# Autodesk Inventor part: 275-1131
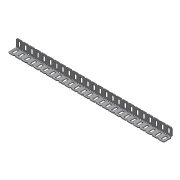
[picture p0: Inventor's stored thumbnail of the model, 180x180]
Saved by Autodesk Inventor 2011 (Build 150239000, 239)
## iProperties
Company: Autodesk Inc.
Created: 2005-08
Part Number: 275-1131
Document SubType Name: Sheet Metal
Designer: Autodesk Inc.
Density: 1 g/cm^3
Sheet Metal Rule: Default
Catalog Web Link: http://www.vexrobotics.com/products/accessories/structure/275-1131.html
Description: VEX angle without slots. Typically used for structural framing. Good strength on two axis.
Vendor: Innovation First, Inc.
Author: Autodesk Inc.
Title: VEX Robotics Kit of Parts
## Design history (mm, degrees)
node "Face1"
  sketch "Sketch1" dims "d23" = 25.4
    geometry: L1 (-154.686, 13.081)-(-150.114, 13.081); L2 (-150.114, 13.081)-(-150.114, 3.302); L3 (-150.114, 3.302)-(-154.686, 3.302); L4 (-154.686, 3.302)-(-154.686, 13.081); L5 (-158.75, 14.605)-(-158.75, 0); L6 (158.75, 14.605)-(158.75, 0); L7 (-158.75, 0)-(158.75, 0); L8 (-156.845, 16.51)-(-158.75, 14.605); L9 (-141.986, 3.302)-(-141.986, 13.081); L10 (-137.414, 3.302)-(-141.986, 3.302); L11 (-137.414, 13.081)-(-137.414, 3.302); L12 (-141.986, 13.081)-(-137.414, 13.081); L13 (-129.286, 3.302)-(-129.286, 13.081); L14 (-124.714, 3.302)-(-129.286, 3.302); L15 (-124.714, 13.081)-(-124.714, 3.302); L16 (-129.286, 13.081)-(-124.714, 13.081); L17 (-116.586, 3.302)-(-116.586, 13.081); L18 (-112.014, 3.302)-(-116.586, 3.302); L19 (-112.014, 13.081)-(-112.014, 3.302); L20 (-116.586, 13.081)-(-112.014, 13.081); L21 (-103.886, 3.302)-(-103.886, 13.081); L22 (-99.314, 3.302)-(-103.886, 3.302); L23 (-99.314, 13.081)-(-99.314, 3.302); L24 (-103.886, 13.081)-(-99.314, 13.081); L25 (-91.186, 3.302)-(-91.186, 13.081); L26 (-86.614, 3.302)-(-91.186, 3.302); L27 (-86.614, 13.081)-(-86.614, 3.302); L28 (-91.186, 13.081)-(-86.614, 13.081); L29 (-78.486, 3.302)-(-78.486, 13.081); L30 (-73.914, 3.302)-(-78.486, 3.302); L31 (-73.914, 13.081)-(-73.914, 3.302); L32 (-78.486, 13.081)-(-73.914, 13.081); L33 (-65.786, 3.302)-(-65.786, 13.081); L34 (-61.214, 3.302)-(-65.786, 3.302); L35 (-61.214, 13.081)-(-61.214, 3.302); L36 (-65.786, 13.081)-(-61.214, 13.081); L37 (-53.086, 3.302)-(-53.086, 13.081); L38 (-48.514, 3.302)-(-53.086, 3.302); L39 (-48.514, 13.081)-(-48.514, 3.302); L40 (-53.086, 13.081)-(-48.514, 13.081); L41 (-40.386, 3.302)-(-40.386, 13.081); L42 (-35.814, 3.302)-(-40.386, 3.302); L43 (-35.814, 13.081)-(-35.814, 3.302); L44 (-40.386, 13.081)-(-35.814, 13.081); L45 (-27.686, 3.302)-(-27.686, 13.081); L46 (-23.114, 3.302)-(-27.686, 3.302); L47 (-23.114, 13.081)-(-23.114, 3.302); L48 (-27.686, 13.081)-(-23.114, 13.081); L49 (-14.986, 3.302)-(-14.986, 13.081); L50 (-10.414, 3.302)-(-14.986, 3.302); L51 (-10.414, 13.081)-(-10.414, 3.302); L52 (-14.986, 13.081)-(-10.414, 13.081); L53 (-2.286, 3.302)-(-2.286, 13.081); L54 (2.286, 3.302)-(-2.286, 3.302); L55 (2.286, 13.081)-(2.286, 3.302); L56 (-2.286, 13.081)-(2.286, 13.081); L57 (10.414, 3.302)-(10.414, 13.081); L58 (14.986, 3.302)-(10.414, 3.302); L59 (14.986, 13.081)-(14.986, 3.302); L60 (10.414, 13.081)-(14.986, 13.081); L61 (23.114, 3.302)-(23.114, 13.081); L62 (27.686, 3.302)-(23.114, 3.302); L63 (27.686, 13.081)-(27.686, 3.302); L64 (23.114, 13.081)-(27.686, 13.081)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; 4 further points
    constraints: 212 end point, 5 parallel, 2 horizontal, 2 perpendicular, 2 point on line, 1 coincident, 1 midpoint, 192 other
    dimensions: "d1" = 4.064 distance between parallel lines of L4 L5; "d2" = 9.779 distance between parallel lines of L3 L1; "d3" = 4.572 distance of L1.start L1.end; "d12" = 16.51 distance of point (-158.75, 16.51) L5.end; "d16" = 1.905 distance of L8.start point (-158.75, 16.51); "d17" = 1.905 distance of L5.start point (-158.75, 16.51) (= d16); "d20" = 12.7 distance of L3.end L9.start; "d28" = 1.905 distance of L6.start point (158.75, 16.51); "d29" = 1.905 distance of L105.end point (158.75, 16.51) (= d28); "d89" = 317.5 distance of L5.end L6.end; "d101" = 3.429 distance between parallel lines of L106 L1; "d102" = 45 deg angle of L104 L105
node "Flange1"
feature "Corner Chamfer1" dims "d38" = 1.905, "d39" = 6.35, angle "d40" = 45 deg
sketch "Sketch3" dims "d112" = 25.4
  geometry: L1 (0, 0)-(0, -13.741) reference; L2 (1.905, -15.646)-(315.595, -15.646) reference; L3 (4.064, -12.217)-(8.636, -12.217); L4 (8.636, -12.217)-(8.636, -2.438); L5 (8.636, -2.438)-(4.064, -2.438); L6 (4.064, -2.438)-(4.064, -12.217); L7 (16.764, -12.217)-(21.336, -12.217); L8 (21.336, -12.217)-(21.336, -2.438); L9 (21.336, -2.438)-(16.764, -2.438); L10 (16.764, -2.438)-(16.764, -12.217); L11 (29.464, -12.217)-(34.036, -12.217); L12 (34.036, -12.217)-(34.036, -2.438); L13 (34.036, -2.438)-(29.464, -2.438); L14 (29.464, -2.438)-(29.464, -12.217); L15 (42.164, -12.217)-(46.736, -12.217); L16 (46.736, -12.217)-(46.736, -2.438); L17 (46.736, -2.438)-(42.164, -2.438); L18 (42.164, -2.438)-(42.164, -12.217); L19 (54.864, -12.217)-(59.436, -12.217); L20 (59.436, -12.217)-(59.436, -2.438); L21 (59.436, -2.438)-(54.864, -2.438); L22 (54.864, -2.438)-(54.864, -12.217); L23 (67.564, -12.217)-(72.136, -12.217); L24 (72.136, -12.217)-(72.136, -2.438); L25 (72.136, -2.438)-(67.564, -2.438); L26 (67.564, -2.438)-(67.564, -12.217); L27 (80.264, -12.217)-(84.836, -12.217); L28 (84.836, -12.217)-(84.836, -2.438); L29 (84.836, -2.438)-(80.264, -2.438); L30 (80.264, -2.438)-(80.264, -12.217); L31 (92.964, -12.217)-(97.536, -12.217); L32 (97.536, -12.217)-(97.536, -2.438); L33 (97.536, -2.438)-(92.964, -2.438); L34 (92.964, -2.438)-(92.964, -12.217); L35 (105.664, -12.217)-(110.236, -12.217); L36 (110.236, -12.217)-(110.236, -2.438); L37 (110.236, -2.438)-(105.664, -2.438); L38 (105.664, -2.438)-(105.664, -12.217); L39 (118.364, -12.217)-(122.936, -12.217); L40 (122.936, -12.217)-(122.936, -2.438); L41 (122.936, -2.438)-(118.364, -2.438); L42 (118.364, -2.438)-(118.364, -12.217); L43 (131.064, -12.217)-(135.636, -12.217); L44 (135.636, -12.217)-(135.636, -2.438); L45 (135.636, -2.438)-(131.064, -2.438); L46 (131.064, -2.438)-(131.064, -12.217); L47 (143.764, -12.217)-(148.336, -12.217); L48 (148.336, -12.217)-(148.336, -2.438); L49 (148.336, -2.438)-(143.764, -2.438); L50 (143.764, -2.438)-(143.764, -12.217); L51 (156.464, -12.217)-(161.036, -12.217); L52 (161.036, -12.217)-(161.036, -2.438); L53 (161.036, -2.438)-(156.464, -2.438); L54 (156.464, -2.438)-(156.464, -12.217); L55 (169.164, -12.217)-(173.736, -12.217); L56 (173.736, -12.217)-(173.736, -2.438); L57 (173.736, -2.438)-(169.164, -2.438); L58 (169.164, -2.438)-(169.164, -12.217); L59 (181.864, -12.217)-(186.436, -12.217); L60 (186.436, -12.217)-(186.436, -2.438); L61 (186.436, -2.438)-(181.864, -2.438); L62 (181.864, -2.438)-(181.864, -12.217); L63 (194.564, -12.217)-(199.136, -12.217); L64 (199.136, -12.217)-(199.136, -2.438)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
  constraints: 200 end point, 2 horizontal, 2 parallel, 1 perpendicular, 192 other
  dimensions: "d103" = 4.572 distance of L3.start L3.end; "d104" = 4.064 distance between parallel lines of L1 L6; "d105" = 3.429 distance between parallel lines of L2 L3; "d106" = 9.779 distance of L5.end L3.start; "d109" = 12.7 distance of L3.start L7.start
cut "Cut1" sketch "Sketch3" dims "d69" = 1.27 (= Thickness), "d70" = 0
sketch "Sketch5" dims "d99" = 25.4
  geometry: L1 (0, 0)-(317.5, 0); L2 (0, 0)-(0, -13.741) reference; L3 (10.795, 1.118)-(12.7, -0.787); L4 (12.7, -0.787)-(14.605, 1.118); L5 (14.605, 1.118)-(12.7, 3.023); L6 (12.7, 3.023)-(10.795, 1.118); L7 (25.4, -0.787)-(27.305, 1.118); L8 (23.495, 1.118)-(25.4, -0.787); L9 (27.305, 1.118)-(25.4, 3.023); L10 (25.4, 3.023)-(23.495, 1.118); L11 (38.1, -0.787)-(40.005, 1.118); L12 (36.195, 1.118)-(38.1, -0.787); L13 (40.005, 1.118)-(38.1, 3.023); L14 (38.1, 3.023)-(36.195, 1.118); L15 (50.8, -0.787)-(52.705, 1.118); L16 (48.895, 1.118)-(50.8, -0.787); L17 (52.705, 1.118)-(50.8, 3.023); L18 (50.8, 3.023)-(48.895, 1.118); L19 (63.5, -0.787)-(65.405, 1.118); L20 (61.595, 1.118)-(63.5, -0.787); L21 (65.405, 1.118)-(63.5, 3.023); L22 (63.5, 3.023)-(61.595, 1.118); L23 (76.2, -0.787)-(78.105, 1.118); L24 (74.295, 1.118)-(76.2, -0.787); L25 (78.105, 1.118)-(76.2, 3.023); L26 (76.2, 3.023)-(74.295, 1.118); L27 (88.9, -0.787)-(90.805, 1.118); L28 (86.995, 1.118)-(88.9, -0.787); L29 (90.805, 1.118)-(88.9, 3.023); L30 (88.9, 3.023)-(86.995, 1.118); L31 (101.6, -0.787)-(103.505, 1.118); L32 (99.695, 1.118)-(101.6, -0.787); L33 (103.505, 1.118)-(101.6, 3.023); L34 (101.6, 3.023)-(99.695, 1.118); L35 (114.3, -0.787)-(116.205, 1.118); L36 (112.395, 1.118)-(114.3, -0.787); L37 (116.205, 1.118)-(114.3, 3.023); L38 (114.3, 3.023)-(112.395, 1.118); L39 (127, -0.787)-(128.905, 1.118); L40 (125.095, 1.118)-(127, -0.787); L41 (128.905, 1.118)-(127, 3.023); L42 (127, 3.023)-(125.095, 1.118); L43 (139.7, -0.787)-(141.605, 1.118); L44 (137.795, 1.118)-(139.7, -0.787); L45 (141.605, 1.118)-(139.7, 3.023); L46 (139.7, 3.023)-(137.795, 1.118); L47 (152.4, -0.787)-(154.305, 1.118); L48 (150.495, 1.118)-(152.4, -0.787); L49 (154.305, 1.118)-(152.4, 3.023); L50 (152.4, 3.023)-(150.495, 1.118); L51 (165.1, -0.787)-(167.005, 1.118); L52 (163.195, 1.118)-(165.1, -0.787); L53 (167.005, 1.118)-(165.1, 3.023); L54 (165.1, 3.023)-(163.195, 1.118); L55 (177.8, -0.787)-(179.705, 1.118); L56 (175.895, 1.118)-(177.8, -0.787); L57 (179.705, 1.118)-(177.8, 3.023); L58 (177.8, 3.023)-(175.895, 1.118); L59 (190.5, -0.787)-(192.405, 1.118); L60 (188.595, 1.118)-(190.5, -0.787); L61 (192.405, 1.118)-(190.5, 3.023); L62 (190.5, 3.023)-(188.595, 1.118); L63 (203.2, -0.787)-(205.105, 1.118); L64 (201.295, 1.118)-(203.2, -0.787)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; 1 further point
  constraints: 210 end point, 4 parallel, 4 perpendicular, 3 horizontal alignment, 1 horizontal, 1 point on line, 192 other
  dimensions: "d91" = 1.905 horizontal distance of L5.end L3.start; "d92" = 1.1176 distance from line of L1 L3.start; "d93" = 12.7 distance from line of L2 L5.end; "d96" = 12.7 distance of L3.end L7.start; "d125" = 1.905 horizontal distance of L100.end L101.end
cut "Cut2" sketch "Sketch5" dims "d84" = 1.27 (= Thickness), "d85" = 0
sketch "Sketch6" dims "d121" = 25.4
  geometry: L1 (0, 0)-(313.69, 0) reference; L2 (-1.905, -15.646)-(-1.905, -1.905) reference; L3 (35.407, -15.646)-(36.195, -14.858) reference; L4 (298.831, -13.208)-(294.259, -13.208) reference; L5 (10.795, -1.905)-(8.89, 0); L6 (10.795, -1.905)-(12.7, 0); L7 (12.7, 0)-(8.89, 0); L8 (23.495, -1.905)-(25.4, 0); L9 (23.495, -1.905)-(21.59, 0); L10 (25.4, 0)-(21.59, 0); L11 (36.195, -1.905)-(38.1, 0); L12 (36.195, -1.905)-(34.29, 0); L13 (38.1, 0)-(34.29, 0); L14 (48.895, -1.905)-(50.8, 0); L15 (48.895, -1.905)-(46.99, 0); L16 (50.8, 0)-(46.99, 0); L17 (61.595, -1.905)-(63.5, 0); L18 (61.595, -1.905)-(59.69, 0); L19 (63.5, 0)-(59.69, 0); L20 (74.295, -1.905)-(76.2, 0); L21 (74.295, -1.905)-(72.39, 0); L22 (76.2, 0)-(72.39, 0); L23 (86.995, -1.905)-(88.9, 0); L24 (86.995, -1.905)-(85.09, 0); L25 (88.9, 0)-(85.09, 0); L26 (99.695, -1.905)-(101.6, 0); L27 (99.695, -1.905)-(97.79, 0); L28 (101.6, 0)-(97.79, 0); L29 (112.395, -1.905)-(114.3, 0); L30 (112.395, -1.905)-(110.49, 0); L31 (114.3, 0)-(110.49, 0); L32 (125.095, -1.905)-(127, 0); L33 (125.095, -1.905)-(123.19, 0); L34 (127, 0)-(123.19, 0); L35 (137.795, -1.905)-(139.7, 0); L36 (137.795, -1.905)-(135.89, 0); L37 (139.7, 0)-(135.89, 0); L38 (150.495, -1.905)-(152.4, 0); L39 (150.495, -1.905)-(148.59, 0); L40 (152.4, 0)-(148.59, 0); L41 (163.195, -1.905)-(165.1, 0); L42 (163.195, -1.905)-(161.29, 0); L43 (165.1, 0)-(161.29, 0); L44 (175.895, -1.905)-(177.8, 0); L45 (175.895, -1.905)-(173.99, 0); L46 (177.8, 0)-(173.99, 0); L47 (188.595, -1.905)-(190.5, 0); L48 (188.595, -1.905)-(186.69, 0); L49 (190.5, 0)-(186.69, 0); L50 (201.295, -1.905)-(203.2, 0); L51 (201.295, -1.905)-(199.39, 0); L52 (203.2, 0)-(199.39, 0); L53 (213.995, -1.905)-(215.9, 0); L54 (213.995, -1.905)-(212.09, 0); L55 (215.9, 0)-(212.09, 0); L56 (226.695, -1.905)-(228.6, 0); L57 (226.695, -1.905)-(224.79, 0); L58 (228.6, 0)-(224.79, 0); L59 (239.395, -1.905)-(241.3, 0); L60 (239.395, -1.905)-(237.49, 0); L61 (241.3, 0)-(237.49, 0); L62 (252.095, -1.905)-(254, 0); L63 (252.095, -1.905)-(250.19, 0); L64 (254, 0)-(250.19, 0)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; 1 further point
  constraints: 144 end point, 2 perpendicular, 2 point on line, 1 horizontal, 1 parallel, 138 other
  dimensions: "d114" = 1.905 horizontal distance of L5.start L5.end; "d115" = 12.7 distance from line of L2 L5.start; "d118" = 12.7 distance of L6.end L8.end
cut "Cut3" sketch "Sketch6" dims "d123" = 1.27 (= Thickness), "d124" = 0
sketch "Sketch7" dims "d133" = 25.4
  geometry: L1 (-1.905, 14.859)-(-1.905, 1.905) reference; L2 (0, 0)-(313.69, 0) reference; L3 (48.895, 14.859)-(48.108, 15.646) reference; L4 (12.7, 0)-(10.795, 1.905); L5 (10.795, 1.905)-(8.89, 0); L6 (8.89, 0)-(12.7, 0); L7 (25.4, 0)-(23.495, 1.905); L8 (23.495, 1.905)-(21.59, 0); L9 (21.59, 0)-(25.4, 0); L10 (38.1, 0)-(36.195, 1.905); L11 (36.195, 1.905)-(34.29, 0); L12 (34.29, 0)-(38.1, 0); L13 (50.8, 0)-(48.895, 1.905); L14 (48.895, 1.905)-(46.99, 0); L15 (46.99, 0)-(50.8, 0); L16 (63.5, 0)-(61.595, 1.905); L17 (61.595, 1.905)-(59.69, 0); L18 (59.69, 0)-(63.5, 0); L19 (76.2, 0)-(74.295, 1.905); L20 (74.295, 1.905)-(72.39, 0); L21 (72.39, 0)-(76.2, 0); L22 (88.9, 0)-(86.995, 1.905); L23 (86.995, 1.905)-(85.09, 0); L24 (85.09, 0)-(88.9, 0); L25 (101.6, 0)-(99.695, 1.905); L26 (99.695, 1.905)-(97.79, 0); L27 (97.79, 0)-(101.6, 0); L28 (114.3, 0)-(112.395, 1.905); L29 (112.395, 1.905)-(110.49, 0); L30 (110.49, 0)-(114.3, 0); L31 (127, 0)-(125.095, 1.905); L32 (125.095, 1.905)-(123.19, 0); L33 (123.19, 0)-(127, 0); L34 (139.7, 0)-(137.795, 1.905); L35 (137.795, 1.905)-(135.89, 0); L36 (135.89, 0)-(139.7, 0); L37 (152.4, 0)-(150.495, 1.905); L38 (150.495, 1.905)-(148.59, 0); L39 (148.59, 0)-(152.4, 0); L40 (165.1, 0)-(163.195, 1.905); L41 (163.195, 1.905)-(161.29, 0); L42 (161.29, 0)-(165.1, 0); L43 (177.8, 0)-(175.895, 1.905); L44 (175.895, 1.905)-(173.99, 0); L45 (173.99, 0)-(177.8, 0); L46 (190.5, 0)-(188.595, 1.905); L47 (188.595, 1.905)-(186.69, 0); L48 (186.69, 0)-(190.5, 0); L49 (203.2, 0)-(201.295, 1.905); L50 (201.295, 1.905)-(199.39, 0); L51 (199.39, 0)-(203.2, 0); L52 (215.9, 0)-(213.995, 1.905); L53 (213.995, 1.905)-(212.09, 0); L54 (212.09, 0)-(215.9, 0); L55 (228.6, 0)-(226.695, 1.905); L56 (226.695, 1.905)-(224.79, 0); L57 (224.79, 0)-(228.6, 0); L58 (241.3, 0)-(239.395, 1.905); L59 (239.395, 1.905)-(237.49, 0); L60 (237.49, 0)-(241.3, 0); L61 (254, 0)-(252.095, 1.905); L62 (252.095, 1.905)-(250.19, 0); L63 (250.19, 0)-(254, 0); L64 (266.7, 0)-(264.795, 1.905)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; 1 further point
  constraints: 144 end point, 2 point on line, 1 collinear, 1 horizontal, 1 parallel, 1 perpendicular, 138 other
  dimensions: "d126" = 12.7 distance from line of L1 L4.end; "d127" = 1.905 horizontal distance of L4.end L5.end; "d130" = 12.7 distance of L4.end L7.end
cut "Cut4" sketch "Sketch7" dims "d135" = 1.27 (derived), "d136" = 0
body "Solid1"
face "Plate1" dims "Thickness" = 1.27
sketch "Sketch2"
  geometry: L1 (317.5, 0)-(317.5, 16.51); L2 (317.5, 16.51)-(0, 16.51); 2 other entities
  constraints: 4 end point, 4 other
face "Plate2" dims "d31" = 1.27 (= BendReliefWidth), "d33" = 2.54 (= MinimumRemnant), "d35" = 16.51, "d36" = 90 deg, "d37" = 0.8636, "Thickness" = 1.27
bend "Bend1" dims "d31" = 1.27 (= BendReliefWidth), "d32" = 0.635 (= BendReliefDepth), "d33" = 2.54 (= MinimumRemnant), "d34" = 1.27 (= BendRadius), "d35" = 16.51, "d36" = 90 deg, "d37" = 0.8636, "SeamGap" = 0.00508, "Thickness" = 1.27
other parameters: "BendRadius" = 1.27 (= Thickness), "BendReliefWidth" = 1.27 (= Thickness), "BendReliefDepth" = 0.635 (= 0.5 x Thickness), "CornerReliefSize" = 5.08 (= 4 x Thickness), "MinimumRemnant" = 2.54 (= 2 x Thickness), "TransitionRadius" = 1.27 (= BendRadius), "d30" = 1.27 (= BendRadius), "JacobiRadiusSize" = 1.27 (= Thickness), "GapSize" = 1.27 (= Thickness)
